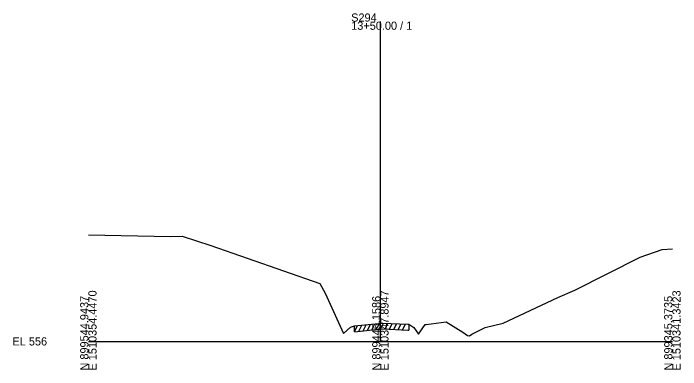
# Model space of a CAD drawing. Extents: x 974 to 2203, y -10 to 19041.
# Drawn here: x 974.3 to 1202.8, y 6990.3 to 7112.5 of the extents above; entities that cross this region are included whole.
import ezdxf

# ---------------------------------------------------------------- set-up
doc = ezdxf.new("R2010")
doc.units = 0
for name, color, linetype in [('RD_GPK_XS_Cell', 7, 'Continuous'), ('RD_XS_ExGround', 7, 'Continuous'), ('RD_XS_ExPaveRet', 7, 'Continuous'), ('RD_XS_TX_Elev_EX', 7, 'Continuous')]:
    doc.layers.add(name, color=color, linetype=linetype)

msp = doc.modelspace()

# ---------------------------------------------------------------- linework, layer by layer
at = {"layer": 'RD_GPK_XS_Cell'}
for p, q in [((1100, 7000), (1100, 7109.61)), ((1000, 7000), (1100, 7000)), ((1100, 7000), (1200, 7000))]:
    msp.add_line(p, q, dxfattribs=at)
at = {"layer": 'RD_XS_ExGround'}
msp.add_lwpolyline([(1000, 7036.54), (1028.09, 7035.9), (1032.13, 7036.12), (1041.96, 7032.91), (1079.22, 7019.86), (1081.06, 7016.55), (1087.38, 7002.66), (1089.81, 7004.83), (1091.1, 7005.3), (1099.35, 7006.14), (1100, 7006.2), (1100.83, 7006.28), (1109.45, 7005.88), (1109.8, 7005.86), (1111.42, 7004.75), (1113.03, 7002.45), (1115.37, 7005.74), (1115.73, 7005.8), (1122.59, 7006.67), (1128.25, 7003.13), (1129.88, 7001.98), (1130.49, 7001.94), (1131.37, 7002.53), (1135.93, 7004.73), (1142.08, 7006.23), (1160.79, 7015.04), (1166.55, 7017.61), (1188.95, 7028.89), (1196.52, 7031.45), (1200, 7031.77)], dxfattribs=at)
at = {"layer": 'RD_XS_ExPaveRet'}
for p, q in [((1091.1, 7003.3), (1092.15, 7005.4)), ((1091.1, 7003.3), (1091.1, 7005.3)), ((1092.6, 7003.45), (1093.65, 7005.56)), ((1094.1, 7003.6), (1095.15, 7005.71)), ((1095.6, 7003.76), (1096.65, 7005.86)), ((1097.1, 7003.91), (1098.15, 7006.02)), ((1098.6, 7004.06), (1099.65, 7006.17)), ((1100.1, 7004.21), (1101.13, 7006.26)), ((1101.6, 7004.24), (1102.58, 7006.2)), ((1103.1, 7004.17), (1104.08, 7006.13)), ((1104.6, 7004.1), (1105.58, 7006.06)), ((1106.1, 7004.04), (1107.08, 7005.99)), ((1107.6, 7003.97), (1108.58, 7005.92)), ((1109.8, 7005.86), (1109.8, 7003.86)), ((1091.1, 7003.3), (1099.35, 7004.14)), ((1099.35, 7004.14), (1100, 7004.2)), ((1100, 7004.2), (1100.83, 7004.28)), ((1100.83, 7004.28), (1109.45, 7003.88)), ((1109.45, 7003.88), (1109.8, 7003.86)), ((1109.8, 7003.86), (1109.8, 7003.86))]:
    msp.add_line(p, q, dxfattribs=at)

# ---------------------------------------------------------------- texts
at = {"layer": 'RD_GPK_XS_Cell'}
for s, p in [('S294', (1090, 7109.61)), ('13+50.00 / 1', (1090, 7106.81)), ('EL 556', (974, 6998.6))]:
    msp.add_text(s, height=2.8, dxfattribs=at).set_placement(p)
for s, p in [('E 1510354.4470', (1002.8, 6990)), ('E 1510347.8947', (1102.8, 6990)), ('E 1510341.3423', (1202.8, 6990)), ('N 899544.9437', (1000, 6990)), ('N 899445.1586', (1100, 6990)), ('N 899345.3735', (1200, 6990))]:
    msp.add_text(s, height=2.8, rotation=90, dxfattribs=at).set_placement(p)
at = {"layer": 'RD_XS_TX_Elev_EX'}
msp.add_text('559.10', height=0.75, rotation=90, dxfattribs=at).set_placement((1100, 7006.2))

doc.saveas('drawing.dxf')
